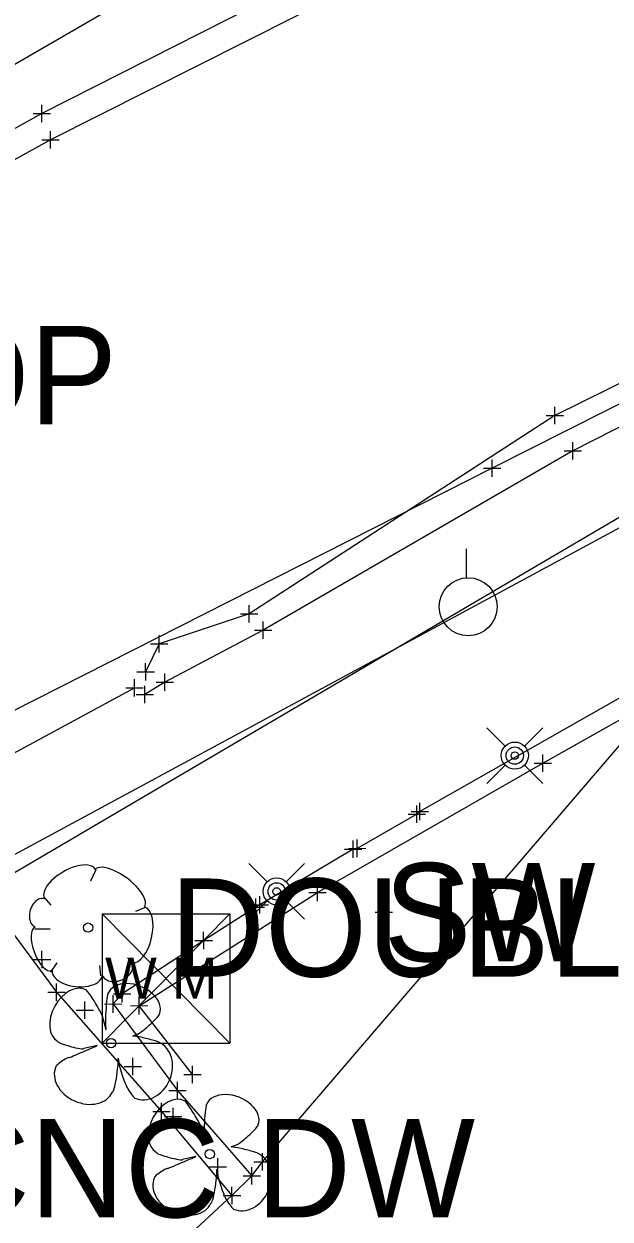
# Model space of a CAD drawing. Extents: x -1 to 1157254, y -1 to 2021979.
# Drawn here: x 1148693.5 to 1148736.4, y 2018237.2 to 2018324.7 of the extents above; entities that cross this region are included whole.
import ezdxf

# ---------------------------------------------------------------- set-up
doc = ezdxf.new("R2010")
doc.units = 0
for name, color, linetype in [('S_BUILDING_ANNOT', 7, 'Continuous'), ('S_CAL_CORNER_ANNOT', 7, 'Continuous'), ('S_CATCH_BASIN', 7, 'Continuous'), ('S_CONTOUR_ANNOT', 7, 'Continuous'), ('S_CURB', 7, 'Continuous'), ('S_DRG_PT_SYM', 7, 'Continuous'), ('S_DRIVEWAY_ANNOT', 7, 'Continuous'), ('S_DROP_INLET', 7, 'Continuous'), ('S_DROP_INLET_ANNOT', 7, 'Continuous'), ('S_EDGE_BITUMINOUS', 7, 'Continuous'), ('S_EDGE_BITUMINOUS_ANNOT', 7, 'Continuous'), ('S_ENV_CONSTRAINT', 7, 'Continuous'), ('S_EXISTING_ALIGNMENT_ANNOT', 7, 'Continuous'), ('S_FENCE', 7, 'Continuous'), ('S_GAS_PUMP_ISLAND_ANNOT', 7, 'Continuous'), ('S_GATE', 7, 'Continuous'), ('S_GATE_ANNOT', 7, 'Continuous')]:
    doc.layers.add(name, color=color, linetype=linetype)

msp = doc.modelspace()

# ---------------------------------------------------------------- linework, layer by layer
at = {"layer": 'S_BUILDING_ANNOT'}
for p, q in [((1148694.812, 2018317.538), (1148694.809, 2018318.811)), ((1148694.174, 2018318.173), (1148695.447, 2018318.176)), ((1148694.81, 2018318.174), (1148694.81, 2018318.174)), ((1148694.794, 2018316.236), (1148696.067, 2018316.239)), ((1148695.432, 2018315.601), (1148695.429, 2018316.873)), ((1148695.43, 2018316.237), (1148695.43, 2018316.237)), ((1148731.763, 2018296.035), (1148733.035, 2018296.038)), ((1148732.4, 2018295.4), (1148732.397, 2018296.673)), ((1148732.399, 2018296.036), (1148732.399, 2018296.036)), ((1148733.062, 2018293.45), (1148734.334, 2018293.453)), ((1148733.699, 2018292.815), (1148733.696, 2018294.088)), ((1148733.698, 2018293.451), (1148733.698, 2018293.451)), ((1148727.804, 2018291.542), (1148727.801, 2018292.815)), ((1148727.166, 2018292.177), (1148728.439, 2018292.18)), ((1148727.803, 2018292.178), (1148727.803, 2018292.178)), ((1148709.997, 2018280.883), (1148709.995, 2018282.155)), ((1148709.36, 2018281.518), (1148710.632, 2018281.52)), ((1148709.996, 2018281.519), (1148709.996, 2018281.519)), ((1148710.382, 2018280.307), (1148711.654, 2018280.309)), ((1148711.019, 2018279.672), (1148711.017, 2018280.944)), ((1148711.018, 2018280.308), (1148711.018, 2018280.308)), ((1148702.764, 2018279.315), (1148704.037, 2018279.318)), ((1148703.402, 2018278.681), (1148703.399, 2018279.953)), ((1148703.401, 2018279.317), (1148703.401, 2018279.317)), ((1148702.414, 2018276.622), (1148702.411, 2018277.894)), ((1148701.591, 2018275.459), (1148701.588, 2018276.732)), ((1148701.776, 2018277.256), (1148703.049, 2018277.259)), ((1148702.413, 2018277.258), (1148702.413, 2018277.258)), ((1148703.823, 2018275.859), (1148703.82, 2018277.132)), ((1148700.953, 2018276.094), (1148702.226, 2018276.097)), ((1148701.59, 2018276.096), (1148701.59, 2018276.096)), ((1148702.364, 2018274.965), (1148702.361, 2018276.238)), ((1148703.185, 2018276.494), (1148704.458, 2018276.497)), ((1148703.822, 2018276.496), (1148703.822, 2018276.496)), ((1148701.726, 2018275.6), (1148702.999, 2018275.603)), ((1148702.363, 2018275.602), (1148702.363, 2018275.602)), ((1148730.88, 2018270.564), (1148732.153, 2018270.567)), ((1148731.518, 2018269.929), (1148731.515, 2018271.202)), ((1148731.517, 2018270.565), (1148731.517, 2018270.565)), ((1148721.864, 2018267.015), (1148723.137, 2018267.018)), ((1148722.278, 2018266.192), (1148722.275, 2018267.465)), ((1148722.502, 2018266.38), (1148722.499, 2018267.653)), ((1148722.5, 2018267.016), (1148722.5, 2018267.016)), ((1148721.64, 2018266.827), (1148722.913, 2018266.83)), ((1148722.276, 2018266.828), (1148722.276, 2018266.828)), ((1148717.609, 2018263.637), (1148717.606, 2018264.91)), ((1148717.908, 2018263.69), (1148717.905, 2018264.963)), ((1148716.971, 2018264.272), (1148718.243, 2018264.275)), ((1148717.27, 2018264.325), (1148718.542, 2018264.328)), ((1148717.607, 2018264.273), (1148717.607, 2018264.273)), ((1148717.906, 2018264.326), (1148717.906, 2018264.326)), ((1148714.999, 2018260.459), (1148714.997, 2018261.731)), ((1148714.362, 2018261.094), (1148715.634, 2018261.097)), ((1148714.998, 2018261.095), (1148714.998, 2018261.095)), ((1148709.846, 2018260.006), (1148711.118, 2018260.008)), ((1148710.15, 2018260.177), (1148711.422, 2018260.179)), ((1148710.483, 2018259.371), (1148710.481, 2018260.643)), ((1148710.482, 2018260.007), (1148710.482, 2018260.007)), ((1148710.787, 2018259.542), (1148710.785, 2018260.814)), ((1148710.786, 2018260.178), (1148710.786, 2018260.178)), ((1148719.859, 2018259.012), (1148719.856, 2018260.284)), ((1148719.221, 2018259.647), (1148720.494, 2018259.649)), ((1148719.857, 2018259.648), (1148719.857, 2018259.648)), ((1148706.027, 2018257.571), (1148707.299, 2018257.573)), ((1148706.664, 2018256.936), (1148706.661, 2018258.208)), ((1148706.663, 2018257.572), (1148706.663, 2018257.572)), ((1148694.821, 2018255.539), (1148694.818, 2018256.811)), ((1148694.183, 2018256.174), (1148695.456, 2018256.176)), ((1148694.819, 2018256.175), (1148694.819, 2018256.175)), ((1148695.883, 2018253.161), (1148695.88, 2018254.433)), ((1148700.687, 2018253.035), (1148700.684, 2018254.307)), ((1148695.245, 2018253.796), (1148696.518, 2018253.798)), ((1148695.881, 2018253.797), (1148695.881, 2018253.797)), ((1148697.951, 2018251.836), (1148697.948, 2018253.108)), ((1148700.028, 2018252.285), (1148700.025, 2018253.557)), ((1148700.049, 2018253.67), (1148701.322, 2018253.672)), ((1148700.686, 2018253.671), (1148700.686, 2018253.671)), ((1148701.929, 2018252.162), (1148701.926, 2018253.434)), ((1148697.313, 2018252.47), (1148698.586, 2018252.473)), ((1148697.95, 2018252.472), (1148697.95, 2018252.472)), ((1148699.39, 2018252.919), (1148700.663, 2018252.922)), ((1148700.026, 2018252.921), (1148700.026, 2018252.921)), ((1148701.291, 2018252.796), (1148702.564, 2018252.799)), ((1148701.928, 2018252.798), (1148701.928, 2018252.798)), ((1148701.465, 2018247.697), (1148701.462, 2018248.97)), ((1148700.827, 2018248.332), (1148702.1, 2018248.335)), ((1148701.464, 2018248.334), (1148701.464, 2018248.334)), ((1148705.203, 2018247.743), (1148706.475, 2018247.746)), ((1148705.84, 2018247.108), (1148705.837, 2018248.381)), ((1148705.839, 2018247.745), (1148705.839, 2018247.745)), ((1148704.737, 2018245.945), (1148704.734, 2018247.218)), ((1148704.099, 2018246.58), (1148705.372, 2018246.583)), ((1148704.736, 2018246.582), (1148704.736, 2018246.582)), ((1148703.572, 2018244.411), (1148703.569, 2018245.684)), ((1148704.436, 2018244.043), (1148704.433, 2018245.316)), ((1148702.934, 2018245.046), (1148704.207, 2018245.049)), ((1148703.571, 2018245.047), (1148703.571, 2018245.047)), ((1148703.798, 2018244.678), (1148705.071, 2018244.681)), ((1148704.435, 2018244.679), (1148704.435, 2018244.679)), ((1148707.701, 2018240.353), (1148707.698, 2018241.626)), ((1148710.976, 2018240.709), (1148710.974, 2018241.982)), ((1148707.064, 2018240.988), (1148708.336, 2018240.991)), ((1148707.7, 2018240.989), (1148707.7, 2018240.989)), ((1148710.203, 2018239.698), (1148710.201, 2018240.971)), ((1148710.339, 2018241.344), (1148711.611, 2018241.347)), ((1148710.975, 2018241.345), (1148710.975, 2018241.345)), ((1148709.566, 2018240.333), (1148710.838, 2018240.336)), ((1148710.202, 2018240.334), (1148710.202, 2018240.334)), ((1148708.739, 2018238.253), (1148708.737, 2018239.526)), ((1148708.102, 2018238.888), (1148709.374, 2018238.891)), ((1148708.738, 2018238.889), (1148708.738, 2018238.889))]:
    msp.add_line(p, q, dxfattribs=at)
at = {"layer": 'S_CAL_CORNER_ANNOT'}
msp.add_lwpolyline([(1148912.938, 2018389.539), (1148884.017, 2018371.372), (1148841.262, 2018348.997), (1148782.551, 2018319.817), (1148727.803, 2018292.178), (1148687.318, 2018271.677), (1148647.965, 2018251.027), (1148473.777, 2018149.564), (1148431.393, 2018121.984), (1148409.202, 2018106.416), (1148303.967, 2018024.033), (1148255.755, 2017987.087), (1148260.87, 2017979.68), (1148255.557, 2017975.255), (1148250.277, 2017982.328), (1148176.106, 2017926.044), (1148136.135, 2017895.283)], dxfattribs=at)
at = {"layer": 'S_CATCH_BASIN'}
msp.add_line((1148725.92, 2018284.171), (1148725.92, 2018286.278), dxfattribs=at)
msp.add_circle((1148726.042, 2018282.031), 2.126, dxfattribs=at)
at = {"layer": 'S_CONTOUR_ANNOT'}
for p, q in [((1148699.238, 2018259.536), (1148708.573, 2018259.536)), ((1148699.238, 2018259.536), (1148699.238, 2018250.046)), ((1148699.238, 2018259.536), (1148708.573, 2018250.046)), ((1148708.573, 2018259.536), (1148699.238, 2018250.046)), ((1148708.573, 2018259.536), (1148708.573, 2018250.046)), ((1148699.238, 2018250.046), (1148708.573, 2018250.046))]:
    msp.add_line(p, q, dxfattribs=at)
at = {"layer": 'S_CURB'}
for p, q in [((1148698.752, 2018262.762), (1148698.365, 2018261.91)), ((1148694.956, 2018260.748), (1148695.46, 2018260.167)), ((1148702.316, 2018259.973), (1148701.657, 2018259.702)), ((1148694.298, 2018258.424), (1148695.421, 2018258.424)), ((1148695.46, 2018255.247), (1148695.925, 2018255.945)), ((1148699.14, 2018254.976), (1148699.062, 2018255.751)), ((1148701.541, 2018255.867), (1148701.076, 2018256.293)), ((1148699.515, 2018251.033), (1148699.271, 2018251.925)), ((1148701.462, 2018250.573), (1148701.841, 2018250.735)), ((1148698.866, 2018249.87), (1148697.892, 2018249.654)), ((1148700.4, 2018248.939), (1148700.478, 2018248.501)), ((1148706.739, 2018242.905), (1148706.496, 2018243.797)), ((1148708.686, 2018242.445), (1148709.065, 2018242.607)), ((1148706.09, 2018241.742), (1148705.116, 2018241.525)), ((1148707.624, 2018240.811), (1148707.703, 2018240.372))]:
    msp.add_line(p, q, dxfattribs=at)
for centre in [(1148698.194, 2018258.518), (1148699.882, 2018250.054), (1148707.107, 2018241.925)]:
    msp.add_circle(centre, 0.34, dxfattribs=at)
for centre, major_axis, ratio, start_param, end_param in [((1148696.859, 2018261.719), (1.856, 1.084), 0.471018, 0, 3.141593), ((1148700.512, 2018261.396), (-1.812, 1.359), 0.405113, 3.141593, 6.283186), ((1148694.625, 2018259.605), (0.305, 1.026), 0.646762, 0, 3.141593), ((1148701.867, 2018257.988), (0.458, 2.039), 0.482994, 3.141593, 6.283185), ((1148694.93, 2018256.956), (-0.61, 1.595), 0.420543, 6.283185, 9.424777), ((1148700.346, 2018255.469), (1.091, 0.462), 0.711534, 3.141592, 6.283185), ((1148697.39, 2018255.176), (-1.831, 0.194), 0.529943, 0, 3.141593), ((1148696.996, 2018252.071), (-1.031, -1.883), 0.662338, 3.141593, 6.283185), ((1148698.649, 2018252.939), (0.622, -1.014), 0.083512, 0, 3.141593), ((1148701.543, 2018252.939), (1.893, -0.744), 0.673998, 0, 3.141593), ((1148699.582, 2018252.358), (-0.068, -1.325), 0.068203, 3.141593, 6.283185), ((1148702.638, 2018251.466), (-0.798, -0.73), 0.092159, 0, 3.141593), ((1148702.422, 2018250.343), (0.96, -0.23), 0.056001, 0, 3.141593), ((1148696.929, 2018249.921), (0.963, -0.267), 0.113563, 3.141593, 6.283185), ((1148697.828, 2018249.427), (1.038, 0.443), 0.002756, 3.141593, 6.283185), ((1148702.5, 2018248.068), (0.882, 2.045), 0.81717, 3.141593, 6.283185), ((1148696.313, 2018248.656), (0.477, 0.328), 0.136309, 0, 3.141593), ((1148700.164, 2018247.774), (0.189, 1.312), 0.114148, 3.141593, 5.822668), ((1148697.906, 2018247.395), (2.069, -0.933), 0.760068, 3.141593, 6.283185), ((1148700.732, 2018247.73), (0.254, -0.771), 0.051603, 3.141593, 6.283185), ((1148701.306, 2018246.493), (-0.321, 0.467), 0.094289, 0, 3.141593), ((1148704.221, 2018243.942), (-1.031, -1.883), 0.662338, 3.141593, 6.283185), ((1148708.767, 2018244.811), (1.893, -0.744), 0.673998, 0, 3.141593), ((1148705.874, 2018244.811), (0.622, -1.014), 0.083512, 0, 3.141593), ((1148706.807, 2018244.23), (-0.068, -1.325), 0.068203, 3.141593, 6.283185), ((1148709.863, 2018243.337), (-0.798, -0.73), 0.092159, 0, 3.141593), ((1148709.646, 2018242.215), (0.96, -0.23), 0.056001, 0, 3.141593), ((1148704.153, 2018241.792), (0.963, -0.267), 0.113563, 3.141593, 6.283185), ((1148705.052, 2018241.299), (1.038, 0.443), 0.002756, 3.141593, 6.283185), ((1148709.724, 2018239.94), (0.882, 2.045), 0.81717, 3.141593, 6.283185), ((1148703.538, 2018240.528), (0.477, 0.328), 0.136309, 0, 3.141593), ((1148707.388, 2018239.646), (0.189, 1.312), 0.114148, 3.141593, 5.822668), ((1148705.13, 2018239.267), (2.069, -0.933), 0.760068, 3.141593, 6.283185), ((1148707.956, 2018239.602), (0.254, -0.771), 0.051603, 3.141593, 6.283185), ((1148708.531, 2018238.364), (-0.321, 0.467), 0.094289, 0, 3.141593)]:
    msp.add_ellipse(centre, major_axis=major_axis, ratio=ratio, start_param=start_param, end_param=end_param, dxfattribs=at)
at = {"layer": 'S_DRG_PT_SYM'}
for p, q in [((1148728.753, 2018271.826), (1148727.411, 2018273.168)), ((1148730.158, 2018271.826), (1148731.5, 2018273.168)), ((1148728.753, 2018270.421), (1148727.411, 2018269.079)), ((1148730.158, 2018270.421), (1148731.5, 2018269.079)), ((1148711.309, 2018261.874), (1148709.967, 2018263.217)), ((1148712.713, 2018261.874), (1148714.055, 2018263.217)), ((1148711.309, 2018260.47), (1148709.967, 2018259.128)), ((1148712.713, 2018260.47), (1148714.055, 2018259.128))]:
    msp.add_line(p, q, dxfattribs=at)
for centre, radius in [((1148729.456, 2018271.123), 0.993), ((1148729.456, 2018271.123), 0.633), ((1148729.456, 2018271.123), 0.273), ((1148712.011, 2018261.172), 0.993), ((1148712.011, 2018261.172), 0.633), ((1148712.011, 2018261.172), 0.273)]:
    msp.add_circle(centre, radius, dxfattribs=at)
at = {"layer": 'S_DRIVEWAY_ANNOT'}
for points in [[(1148930.723, 2018469.064), (1148929.819, 2018466.88), (1148924.632, 2018459.028), (1148905.958, 2018441.115), (1148885.567, 2018425.643), (1148853.786, 2018405.734), (1148817.842, 2018385.163), (1148785.669, 2018366.18), (1148751.531, 2018348.966), (1148725.908, 2018333.965), (1148694.81, 2018318.174), (1148657.764, 2018297.519), (1148609.034, 2018271.575), (1148572.155, 2018252.396), (1148560.689, 2018247.438)], [(1148931.239, 2018467.866), (1148932.006, 2018465.498), (1148926.134, 2018456.229), (1148907.814, 2018438.702), (1148886.938, 2018423.834), (1148854.979, 2018403.628), (1148818.742, 2018383.307), (1148786.468, 2018365.474), (1148752.662, 2018346.947), (1148727.642, 2018332.49), (1148695.43, 2018316.237), (1148658.964, 2018296.013), (1148609.684, 2018269.542), (1148573.054, 2018250.475), (1148561.713, 2018245.724)], [(1148908.369, 2018387.376), (1148906.38, 2018386.692), (1148901.685, 2018384.948), (1148882.867, 2018373.437), (1148846.307, 2018354.115), (1148809.29, 2018334.855), (1148769.484, 2018314.36), (1148732.399, 2018296.036), (1148709.996, 2018281.519), (1148703.401, 2018279.317), (1148702.413, 2018277.258)], [(1148909.686, 2018385.632), (1148907.122, 2018384.988), (1148903.503, 2018382.003), (1148884.61, 2018371.67), (1148846.561, 2018352.222), (1148810.629, 2018333.081), (1148770.151, 2018311.966), (1148733.698, 2018293.451), (1148711.018, 2018280.308), (1148703.822, 2018276.496), (1148702.363, 2018275.602)]]:
    msp.add_lwpolyline(points, dxfattribs=at)
at = {"layer": 'S_DROP_INLET'}
msp.add_lwpolyline([(1149478.883, 2018922.635), (1149385.843, 2018831.357), (1149330.573, 2018775.164), (1149250.597, 2018696.803), (1149231.499, 2018678.754), (1149169.666, 2018614.297), (1149128.449, 2018577.044), (1149075.888, 2018529.44), (1149016.277, 2018476.328), (1148941.338, 2018408.699), (1148861.111, 2018354.7), (1148778.494, 2018311.958), (1148755.862, 2018297.95), (1148577.392, 2018201.518), (1148460.645, 2018136.543), (1148334.568, 2018041.736), (1148195.528, 2017935.768), (1148138.819, 2017892.989)], dxfattribs=at)
at = {"layer": 'S_DROP_INLET_ANNOT'}
msp.add_lwpolyline([(1148647.524, 2018246.828), (1148701.59, 2018276.096)], dxfattribs=at)
at = {"layer": 'S_EDGE_BITUMINOUS'}
msp.add_lwpolyline([(1148749.086, 2018290.005), (1148752.808, 2018284.101), (1148738.547, 2018276.007), (1148738.287, 2018275.993), (1148722.5, 2018267.016), (1148722.276, 2018266.828), (1148717.906, 2018264.326), (1148717.607, 2018264.273), (1148710.786, 2018260.178), (1148710.482, 2018260.007), (1148706.663, 2018257.572), (1148700.686, 2018253.671), (1148700.026, 2018252.921), (1148704.736, 2018246.582), (1148710.202, 2018240.334)], dxfattribs=at)
at = {"layer": 'S_EDGE_BITUMINOUS_ANNOT'}
msp.add_lwpolyline([(1148923.017, 2018461.015), (1148903.038, 2018442.9), (1148882.577, 2018429.219), (1148850.144, 2018409.009), (1148817.086, 2018388.985), (1148781.41, 2018369.695), (1148749.487, 2018356.125), (1148727.388, 2018341.805), (1148692.476, 2018321.568), (1148656.835, 2018301.583), (1148607.373, 2018274.07), (1148571.257, 2018254.745)], dxfattribs=at)
at = {"layer": 'S_ENV_CONSTRAINT'}
msp.add_lwpolyline([(1148688.696, 2018258.567), (1148691.127, 2018260.186), (1148695.881, 2018253.797), (1148703.571, 2018245.047), (1148708.738, 2018238.889)], dxfattribs=at)
at = {"layer": 'S_EXISTING_ALIGNMENT_ANNOT'}
msp.add_lwpolyline([(1148705.839, 2018247.745), (1148701.928, 2018252.798), (1148714.998, 2018261.095), (1148731.517, 2018270.565), (1148743.357, 2018277.231), (1148753.857, 2018283.308), (1148754.808, 2018281.901)], dxfattribs=at)
at = {"layer": 'S_FENCE'}
msp.add_lwpolyline([(1149562.212, 2019005.402), (1149486.208, 2018927.146), (1149466.957, 2018916.396), (1149448.148, 2018887.454), (1149385.385, 2018826.897), (1149357.497, 2018803.658), (1149334.174, 2018772.973), (1149278.678, 2018714.017), (1149266.211, 2018707.986), (1149250.596, 2018696.753), (1149241.457, 2018677.199), (1149179.127, 2018611.741), (1149130.367, 2018567.148), (1149080.157, 2018520.923), (1149020.191, 2018471.531), (1148946.081, 2018397.311), (1148842.281, 2018340.538), (1148783.264, 2018310.714), (1148755.063, 2018299.134), (1148580.086, 2018196.311), (1148464.769, 2018128.057), (1148357.295, 2018049.222), (1148182.052, 2017918.064), (1148146.031, 2017882.736)], dxfattribs=at)
at = {"layer": 'S_GAS_PUMP_ISLAND_ANNOT'}
msp.add_lwpolyline([(1148595.695, 2018221.082), (1148643.977, 2018208.641), (1148686.864, 2018218.655), (1148708.738, 2018238.889), (1148710.202, 2018240.334), (1148710.975, 2018241.345), (1148740.231, 2018275.471), (1148754.808, 2018281.901), (1148784.06, 2018319.221), (1148792.916, 2018323.841), (1148801.772, 2018328.461), (1148810.629, 2018333.081)], dxfattribs=at)

# ---------------------------------------------------------------- texts
at = {"layer": 'S_CONTOUR_ANNOT'}
msp.add_text('W M', height=2.9988, dxfattribs=at).set_placement((1148699.443, 2018253.305))
at = {"layer": 'S_GATE'}
for s, p in [('1 STORY MTL SHOP', (1148607.233, 2018295.4)), ('SW GOES TO BU', (1148719.857, 2018256.048)), ('CNC DW', (1148686.969, 2018237.288))]:
    msp.add_text(s, height=7.2, dxfattribs=at).set_placement(p)
at = {"layer": 'S_GATE_ANNOT'}
msp.add_text('DOUBLE 2" CREPE MYRTLE', height=7.2, dxfattribs=at).set_placement((1148704.194, 2018254.918))

doc.saveas('drawing.dxf')
